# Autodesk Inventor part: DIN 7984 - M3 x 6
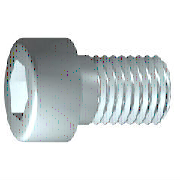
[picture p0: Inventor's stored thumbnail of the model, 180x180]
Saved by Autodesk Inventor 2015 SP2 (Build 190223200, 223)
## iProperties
IsCustomPart: 0
Created: 2012-02
Part Number: DIN 7984 - M3 x 6
Material: Steel, Mild
Description: Cylinder Head Cap Screw
Document SubType Name: Modeling
Standard: DIN 7984
Designer: rYan
Standard Revision: 1985
Standards Organization: DIN
Language: en-US
Size Designation: M3 x 6
Categories: <MemberInstance><Categories><Category DisplayName="Fasteners" InternalName="e4da775c-781d-43d5-af7c-5136215cf5a6" Mnemonic="FSTN"><Category DisplayName="Bolts"
Density: 7.85 g/cm^3
Mass: 0.652401 g
Surface Area: 1.45477 cm^2
Volume: 0.0831084 cm^3
Appearance: Halbpoliert
Author: rYan
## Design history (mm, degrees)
sketch "Sketch1"
  geometry: L1 (0.167, 0)-(6, 0); L2 (6, 0)-(6, 1.5); L3 (6, 1.5)-(1.5, 1.5); L4 (1.5, 1.5)-(1.193, 1.5); L5 (1.193, 1.5)-(0, 1.5); L6 (0, 1.5)-(0, 2.75); L7 (0, 2.75)-(-2, 2.75); L8 (-2, 2.75)-(-2, 1.155); L9 (-2, 1.155)-(-0.5, 1.155); L10 (-0.5, 1.155)-(0.167, 0); L11 (-3.6, 0)-(7.6, 0) reference; L12 (0, -0.55)-(0, 3.3) reference; L13 (1.5, 1.5)-(0, 1.5)
  constraints: 22 end point, 6 parallel, 2 collinear, 2 perpendicular, 1 horizontal, 1 point on line
  dimensions: "d1" = 4.5 distance from line of L3.end L2 (= GEL); "d2" = 0.30683 distance of L4.end L3.end (computed from GAL); "d3" = 2 distance between parallel lines of L8 L6 (= KOH); "d4" = 1.5 distance of L8.end L9.end (= INTI); "d5" = 60 deg angle of L10 L1; "d6" = 3 diameter of L3 L1 (= GD); "d7" = 3 diameter of L5 L1 (= BDM); "d8" = 2.3094 diameter of L9 L1 (= 1.1547 x SW); "d9" = 5.5 diameter of L7 L1 (= KOD); "d26" = 6 distance between parallel lines of L12 L2 (= NLG)
revolve "Body" sketch "Sketch1" stored, may be unused: angle "d10" = 90 deg
sketch "Sketch2"
  geometry: L1 (0, -3.85)-(0, 3.85) reference; L2 (-3.85, 0)-(3.85, 0) reference; L3 (1.155, 0)-(0.577, -1); L4 (0.577, -1)-(-0.577, -1); L5 (-0.577, -1)-(-1.155, 0); L6 (-1.155, 0)-(-0.577, 1); L7 (-0.577, 1)-(0.577, 1); L8 (0.577, 1)-(1.155, 0); 2 further points
  constraints: 12 end point, 1 coincident, 1 horizontal alignment, 1 point on line, 12 other
extrude "Slot" join sketch "Sketch2" stored distance "d11" = 10; taper "d12" = 0 deg
fillet "Fillet1" dims "d17" = 0.3 (= RR)
feature "Thread" dims "d13" = 4.5 (= GEL), "d14" = 0
chamfer "Chamfer1" distance "d15" = 0.30673 (= -0.5 x SPD + 0.5 x GD); stored, may be unused: second distance "d16" = 0.30673 (= GUL), angle "d27" = 45 deg
workplane "Work Plane1"
fillet "Fillet2" dims "d30" = 0.1 (= R)
body "Solid1"
other parameters: "GD" = 3 (= NND) [user parameter; used in 2 equation terms], "NLG" = 6 [user parameter; used in 1 equation term], "GEL" = 4.5 [user parameter; used in 2 equation terms], "KOD" = 5.5 [user parameter; used in 1 equation term], "KOH" = 2 [user parameter; used in 1 equation term], "INTI" = 1.5 [user parameter; used in 1 equation term], "GAL" = 0.30673 (= 0.61345 x PTC) [user parameter; used in 1 equation term], "GUL" = 0.30673 (= 0.61345 x PTC) [user parameter; used in 1 equation term], "BDM" = 3 (= NND) [user parameter; used in 1 equation term], "SW" = 2 [user parameter; used in 2 equation terms], "RR" = 0.3 [user parameter; used in 1 equation term], "SPD" = 2.38655 (= NND - 1.2269 x PTC) [user parameter; used in 1 equation term], "d19" = 0, "d28" = 0, "d29" = 0, "R" = 0.1 [user parameter; used in 1 equation term], "TOA" = 30 deg [user parameter], "GD1" = 2.38655 (= THREADDIA - 1.2269 x PTC) [user parameter], "THREADDIA" = 3 [user parameter; used in 1 equation term], "FAWI" = 45 deg [user parameter], "ANG" = 120 deg [user parameter], "PTC" = 0.5 [user parameter; used in 5 equation terms], "NND" = 3 [user parameter; used in 3 equation terms], "E0" = 2.31 (= 1.155 x SW) [user parameter]
